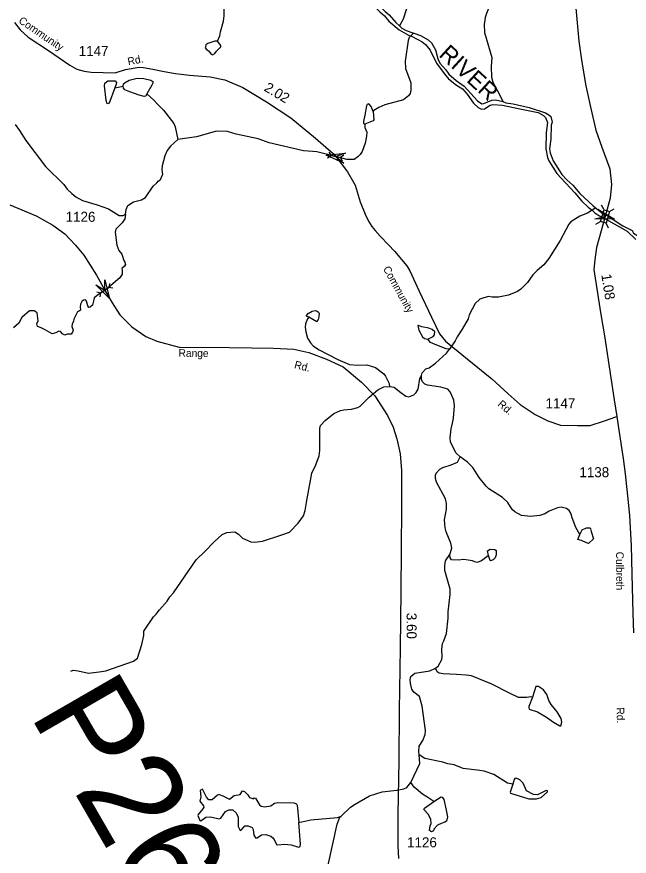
# Model space of a CAD drawing. Extents: x 2056842 to 2160602, y 826753 to 1016856.
# Drawn here: x 2071991 to 2079635, y 918502 to 928971 of the extents above; entities that cross this region are included whole.
import ezdxf

# ---------------------------------------------------------------- set-up
doc = ezdxf.new("R2010")
doc.units = 0
for name, color, linetype in [('Exist Hydrographic Creek Single Shore', 7, 'Continuous'), ('Exist Hydrographic Misc Water Feature', 7, 'Continuous'), ('Exist Hydrographic River Shore', 7, 'Continuous'), ('Exist Hydrographic River Shore Label', 7, 'Continuous'), ('Exist Road Secondary Mileage Hundredths English Label', 7, 'Continuous'), ('Exist Road Secondary Structure Pipe Attributed CELL', 7, 'Continuous'), ('Exist Road Secondary Structure Pipe CELL', 7, 'Continuous'), ('Exist Road Secondary Structure Pipe Number Label', 7, 'Continuous'), ('Exist Road Secondary Structure Standard Bridge Attributed CELL', 7, 'Continuous'), ('Exist Road Secondary Structure Standard Bridge CELL', 7, 'Continuous'), ('Exist Road Secondary Type 51 Attributed', 7, 'Continuous'), ('Exist Road Secondary Type 51 Label', 7, 'Continuous'), ('Exist Road Secondary Type 51 Number Label', 7, 'Continuous')]:
    doc.layers.add(name, color=color, linetype=linetype)

msp = doc.modelspace()

# ---------------------------------------------------------------- linework, layer by layer
at = {"layer": 'Exist Hydrographic Creek Single Shore'}
for points in [[(2078694, 930588), (2078660, 930556), (2078614, 930456), (2078527, 930326), (2078481, 930274), (2078405, 930146), (2078312, 930051), (2078232, 929913), (2078162, 929773), (2078047, 929633), (2078009, 929596), (2077975, 929454), (2077946, 929288), (2077899, 929128), (2077853, 929014), (2077835, 928962), (2077823, 928874), (2077830, 928774), (2077921, 928464), (2077913, 928352), (2077917, 928216), (2077933, 928156), (2078020, 927995), (2078056, 927915)], [(2076942, 928767), (2076890, 928713), (2076876, 928677), (2076839, 928417), (2076843, 928325), (2076909, 928149), (2076908, 928057), (2076900, 928013), (2076880, 927985), (2076816, 927937), (2076586, 927874), (2076510, 927840), (2076448, 927802), (2076439, 927787)], [(2076439, 927788), (2076415, 927854), (2076390, 927881), (2076379, 927885), (2076363, 927877), (2076355, 927861), (2076335, 927745)], [(2076439, 927788), (2076449, 927686), (2076437, 927672), (2076333, 927633)], [(2076335, 927745), (2076317, 927665), (2076317, 927641), (2076333, 927633)], [(2076333, 927633), (2076337, 927589), (2076362, 927533), (2076357, 927481), (2076340, 927397), (2076300, 927289), (2076278, 927255), (2076247, 927225), (2076201, 927193), (2076112, 927191), (2075972, 927228), (2075734, 927285), (2075686, 927293), (2075570, 927299), (2075140, 927401), (2075004, 927451), (2074728, 927506), (2074619, 927542), (2074484, 927543), (2074234, 927474), (2074002, 927440)], [(2074002, 927440), (2073910, 927359), (2073870, 927303), (2073837, 927235), (2073805, 927111), (2073801, 927067), (2073811, 927003), (2073776, 926931), (2073757, 926917)], [(2073350, 926511), (2073356, 926567), (2073378, 926619), (2073446, 926663), (2073546, 926689), (2073596, 926717), (2073695, 926859), (2073741, 926900), (2073759, 926924)], [(2073350, 926511), (2073338, 926452), (2073308, 926402), (2073227, 926321), (2073218, 926283), (2073239, 926123), (2073266, 926055), (2073302, 926012), (2073326, 925933), (2073340, 925912), (2073348, 925883), (2073335, 925862), (2073303, 925833), (2073305, 925809), (2073305, 925762), (2073279, 925714), (2073136, 925595), (2073090, 925562), (2073026, 925522), (2072956, 925466), (2072944, 925408), (2072937, 925376), (2072907, 925348), (2072889, 925344), (2072877, 925365), (2072863, 925425), (2072848, 925440), (2072824, 925438), (2072802, 925419), (2072787, 925385), (2072783, 925354), (2072787, 925314), (2072773, 925302), (2072748, 925291), (2072704, 925198), (2072700, 925173), (2072683, 925136), (2072680, 925110), (2072695, 925064), (2072687, 925037), (2072669, 925012), (2072648, 925014), (2072622, 925014), (2072590, 925001), (2072563, 925019), (2072536, 925046), (2072515, 925051), (2072478, 925028), (2072432, 925019), (2072347, 925065), (2072295, 925093), (2072251, 925109), (2072242, 925140), (2072258, 925180), (2072247, 925277), (2072209, 925304), (2072148, 925304), (2072054, 925221), (2072018, 925150), (2071951, 925093)]]:
    msp.add_lwpolyline(points, dxfattribs=at)
at = {"layer": 'Exist Hydrographic Misc Water Feature'}
for p, q in [((2073215, 928087), (2073317, 928104)), ((2079313, 926463), (2079339, 926501))]:
    msp.add_line(p, q, dxfattribs=at)
for points in [[(2074496, 928667), (2074524, 928732), (2074534, 928785), (2074573, 928916), (2074581, 928984), (2074579, 929092), (2074544, 929258), (2074562, 929360), (2074651, 929524), (2074707, 929598), (2074889, 929787), (2074988, 929833)], [(2076857, 929069), (2076815, 928943), (2076767, 928859)], [(2074496, 928667), (2074464, 928665), (2074376, 928637), (2074352, 928623), (2074346, 928597)], [(2074483, 928543), (2074536, 928596), (2074536, 928612), (2074496, 928667)], [(2074346, 928597), (2074344, 928583), (2074361, 928563), (2074385, 928545), (2074417, 928505), (2074435, 928497), (2074461, 928515), (2074483, 928543)], [(2073317, 928104), (2073325, 928135), (2073343, 928153), (2073394, 928181), (2073493, 928204), (2073578, 928201), (2073665, 928181), (2073688, 928163), (2073688, 928145), (2073678, 928120), (2073615, 928010)], [(2073105, 927929), (2073087, 928111), (2073091, 928143)], [(2073091, 928143), (2073129, 928171), (2073221, 928171), (2073235, 928151), (2073233, 928131), (2073215, 928087)], [(2073215, 928087), (2073145, 927895), (2073118, 927887), (2073105, 927929)], [(2073615, 928010), (2073603, 927981), (2073580, 927979), (2073519, 927992), (2073401, 928035), (2073340, 928061), (2073322, 928081), (2073317, 928104)], [(2073757, 927873), (2073749, 927881), (2073700, 927932), (2073615, 928010)], [(2073757, 927873), (2073823, 927805), (2073953, 927640), (2073968, 927600), (2074002, 927440)], [(2071970, 927628), (2072024, 927553), (2072105, 927429), (2072349, 927105), (2072577, 926880), (2072620, 926822), (2072678, 926766), (2072728, 926726), (2072810, 926678), (2072994, 926626), (2073134, 926575), (2073270, 926491), (2073318, 926491), (2073350, 926511)], [(2079339, 926501), (2079371, 926483), (2079555, 926365), (2079671, 926304), (2079687, 926272), (2079796, 926206), (2079827, 926202), (2079873, 926184), (2079915, 926193), (2079965, 926213), (2080063, 926293), (2080139, 926391), (2080189, 926467), (2080237, 926512), (2080352, 926582), (2080522, 926665), (2080584, 926681)], [(2079217, 926587), (2079116, 926524), (2079019, 926486), (2078907, 926413), (2078883, 926385), (2078773, 926183), (2078630, 925957), (2078571, 925876), (2078485, 925806), (2078433, 925754), (2078365, 925658), (2078283, 925573), (2078240, 925545), (2078128, 925499), (2078004, 925476), (2077924, 925476), (2077880, 925482), (2077808, 925462), (2077772, 925450), (2077710, 925394), (2077639, 925253), (2077623, 925203), (2077551, 925075), (2077487, 924981), (2077462, 924929), (2077390, 924825)], [(2079174, 926560), (2079208, 926524), (2079263, 926487), (2079313, 926463)], [(2075635, 925223), (2075609, 925237), (2075609, 925247), (2075629, 925271), (2075679, 925299)], [(2075679, 925299), (2075717, 925307), (2075739, 925301), (2075757, 925286), (2075763, 925270), (2075759, 925231)], [(2075635, 925223), (2075619, 925203), (2075595, 925143), (2075591, 925101), (2075599, 925043), (2075620, 924963), (2075656, 924903), (2075692, 924867), (2075756, 924822), (2075997, 924696), (2076143, 924635), (2076241, 924627), (2076361, 924629), (2076467, 924596), (2076571, 924518), (2076595, 924490), (2076639, 924398), (2076643, 924362)], [(2075759, 925231), (2075751, 925196), (2075735, 925167), (2075635, 925223)], [(2077177, 925070), (2077135, 925086), (2077047, 925104), (2077005, 925123), (2076997, 925119), (2077003, 925082), (2077009, 925062)], [(2077009, 925062), (2077054, 924980), (2077078, 924960), (2077120, 924950)], [(2077120, 924950), (2077186, 924982), (2077205, 925006), (2077207, 925042), (2077177, 925070)], [(2077390, 924825), (2077350, 924829), (2077214, 924886), (2077154, 924910), (2077120, 924950)], [(2077043, 924498), (2077049, 924530), (2077097, 924582), (2077137, 924594), (2077217, 924650), (2077354, 924777), (2077390, 924825)], [(2076643, 924362), (2076701, 924351), (2076768, 924297), (2076848, 924241), (2076884, 924233), (2076948, 924257), (2076976, 924287), (2077002, 924326), (2077023, 924458), (2077043, 924498)], [(2077524, 923485), (2077472, 923533), (2077404, 923669), (2077398, 923721), (2077411, 923833), (2077431, 923901), (2077441, 923965), (2077452, 924117), (2077444, 924189), (2077422, 924247), (2077398, 924293), (2077370, 924325), (2077285, 924352), (2077117, 924378), (2077085, 924390), (2077053, 924418), (2077043, 924446), (2077043, 924498)], [(2073773, 921575), (2073868, 921684), (2073902, 921738), (2073946, 921786), (2074228, 922199), (2074340, 922303), (2074454, 922422), (2074553, 922514), (2074613, 922538), (2074711, 922548), (2074759, 922519), (2074809, 922469), (2074914, 922423), (2074958, 922417), (2075058, 922433), (2075287, 922506), (2075393, 922543), (2075505, 922657), (2075571, 922747), (2075591, 922813), (2075612, 922937), (2075673, 923281), (2075725, 923382), (2075764, 923494), (2075772, 923562), (2075774, 923682), (2075773, 923838), (2075783, 923874), (2075839, 923938), (2075947, 924022), (2076031, 924062), (2076074, 924071), (2076170, 924079), (2076246, 924097), (2076276, 924113), (2076388, 924226), (2076496, 924318), (2076571, 924358), (2076643, 924362)], [(2077394, 922267), (2077420, 922345), (2077410, 922405), (2077349, 922547), (2077337, 922599), (2077331, 922697), (2077354, 922831), (2077354, 922903), (2077340, 922959), (2077229, 923168), (2077215, 923212), (2077215, 923256), (2077225, 923280), (2077271, 923328), (2077307, 923349), (2077411, 923383), (2077490, 923417), (2077524, 923485)], [(2079019, 922514), (2078967, 922602), (2078921, 922724), (2078908, 922782), (2078884, 922814), (2078850, 922839), (2078784, 922855), (2078738, 922847), (2078636, 922807), (2078580, 922773), (2078518, 922752), (2078403, 922738), (2078290, 922752), (2078206, 922795), (2078172, 922827), (2078120, 922915), (2078052, 922977), (2077881, 923082), (2077848, 923116), (2077763, 923224), (2077683, 923352), (2077616, 923418), (2077524, 923485)], [(2079019, 922514), (2079047, 922572), (2079103, 922598), (2079147, 922598), (2079153, 922586), (2079161, 922552)], [(2079161, 922552), (2079189, 922461), (2079127, 922402), (2079103, 922412)], [(2079103, 922412), (2079041, 922440), (2078995, 922454), (2079019, 922514)], [(2077878, 922254), (2077868, 922310), (2077900, 922330), (2077958, 922329)], [(2077958, 922329), (2077976, 922313), (2077976, 922261), (2077962, 922223)], [(2077219, 920846), (2077250, 920874), (2077294, 920955), (2077302, 920991), (2077298, 921079), (2077304, 921155), (2077321, 921187), (2077355, 921279), (2077377, 921469), (2077374, 921551), (2077402, 921767), (2077399, 921831), (2077333, 922067), (2077333, 922127), (2077340, 922187), (2077394, 922267)], [(2077878, 922254), (2077858, 922234), (2077792, 922186), (2077738, 922166), (2077706, 922172), (2077680, 922184), (2077570, 922203), (2077498, 922195), (2077418, 922197), (2077402, 922223), (2077394, 922267)], [(2077962, 922223), (2077938, 922197), (2077904, 922185), (2077900, 922190), (2077878, 922254)], [(2072667, 920808), (2072693, 920824), (2072759, 920816), (2072885, 920785), (2073019, 920801), (2073103, 920815), (2073449, 920934), (2073497, 920970), (2073552, 921142), (2073576, 921254), (2073578, 921307), (2073698, 921489), (2073729, 921519), (2073773, 921575)], [(2077014, 919766), (2077008, 919806), (2077014, 919874), (2077057, 919946), (2077087, 920022), (2077091, 920070), (2077050, 920372), (2077018, 920494), (2076945, 920548), (2076921, 920587), (2076903, 920655), (2076901, 920707), (2076909, 920743), (2076957, 920784), (2077145, 920816), (2077219, 920846)], [(2078428, 920486), (2078408, 920490), (2078356, 920480), (2078252, 920482), (2078140, 920537), (2077919, 920647), (2077667, 920750), (2077601, 920762), (2077477, 920769), (2077313, 920775), (2077261, 920787), (2077237, 920802), (2077219, 920846)], [(2078632, 920445), (2078607, 920517), (2078563, 920577), (2078503, 920618), (2078471, 920618), (2078428, 920486)], [(2078428, 920486), (2078382, 920368), (2078382, 920352), (2078388, 920338), (2078490, 920302), (2078602, 920237), (2078690, 920173)], [(2078690, 920173), (2078767, 920127), (2078783, 920127), (2078793, 920175), (2078786, 920219), (2078734, 920301), (2078662, 920393), (2078632, 920445)], [(2076911, 919422), (2077020, 919658), (2077014, 919766)], [(2078183, 919400), (2078117, 919413), (2077945, 919521), (2077825, 919564), (2077772, 919572), (2077562, 919594), (2077448, 919641), (2077372, 919655), (2077310, 919675), (2077084, 919722), (2077014, 919766)], [(2076039, 919003), (2076156, 919113), (2076216, 919153), (2076393, 919254), (2076550, 919306), (2076733, 919325), (2076823, 919343), (2076861, 919361), (2076911, 919422)], [(2077196, 919184), (2077110, 919244), (2077054, 919274), (2076951, 919362), (2076911, 919422)], [(2078183, 919400), (2078149, 919299), (2078153, 919287), (2078381, 919216), (2078478, 919217)], [(2078353, 919318), (2078309, 919412), (2078269, 919456), (2078225, 919474), (2078205, 919472), (2078197, 919460), (2078183, 919400)], [(2074516, 919270), (2074496, 919264), (2074430, 919204), (2074386, 919204), (2074360, 919237), (2074311, 919339), (2074280, 919321), (2074288, 919243), (2074274, 919189), (2074322, 919131), (2074324, 919115), (2074314, 919091), (2074254, 919023), (2074250, 919011), (2074277, 918949), (2074289, 918943), (2074351, 918991), (2074407, 918992), (2074519, 918970), (2074539, 918978), (2074594, 919058), (2074638, 919082), (2074686, 919080), (2074731, 919041), (2074755, 918991), (2074755, 918911)], [(2074516, 919270), (2074564, 919254), (2074636, 919218), (2074648, 919214), (2074704, 919259), (2074778, 919273), (2074808, 919319), (2074832, 919311), (2074876, 919267), (2074896, 919235), (2074944, 919219), (2074952, 919229), (2074972, 919227), (2075020, 919142), (2075040, 919126), (2075082, 919118), (2075160, 919130), (2075208, 919164), (2075248, 919172), (2075448, 919169), (2075484, 919155), (2075492, 919139), (2075513, 918921)], [(2078478, 919217), (2078534, 919233), (2078613, 919305), (2078613, 919317), (2078597, 919321), (2078491, 919267), (2078439, 919270), (2078353, 919318)], [(2077163, 918912), (2077159, 918960), (2077130, 919022), (2077072, 919084), (2077080, 919100), (2077196, 919184)], [(2077196, 919184), (2077288, 919241), (2077300, 919237), (2077320, 919211), (2077352, 919077), (2077366, 918993)], [(2075366, 917413), (2075435, 917463), (2075459, 917509), (2075549, 917617), (2075605, 917669), (2075662, 917752), (2075686, 917800), (2075732, 917990), (2075805, 918222), (2075882, 918410), (2075989, 918903), (2076023, 918989), (2076039, 919003)], [(2075513, 918921), (2075661, 918954), (2075995, 918983), (2076039, 919003)], [(2077366, 918993), (2077355, 918941), (2077333, 918925), (2077287, 918909), (2077243, 918889), (2077197, 918840), (2077191, 918820), (2077167, 918808), (2077143, 918824), (2077151, 918880), (2077163, 918912)], [(2074755, 918911), (2074753, 918871), (2074779, 918821), (2074795, 918831), (2074839, 918879), (2074879, 918883), (2074929, 918859), (2074943, 918837), (2074951, 918763), (2074971, 918733), (2074991, 918730), (2075045, 918770), (2075101, 918774), (2075163, 918750), (2075187, 918732), (2075203, 918712), (2075232, 918650), (2075244, 918642), (2075332, 918651), (2075416, 918643), (2075496, 918617), (2075510, 918613), (2075528, 918623), (2075532, 918651), (2075513, 918921)]]:
    msp.add_lwpolyline(points, dxfattribs=at)
at = {"layer": 'Exist Hydrographic River Shore'}
for points in [[(2074988, 929833), (2075069, 929777), (2075169, 929739), (2075321, 929736), (2075417, 929726), (2075553, 929697), (2075791, 929591), (2075963, 929492), (2076034, 929438), (2076190, 929335), (2076280, 929271), (2076521, 929034), (2076579, 928982), (2076635, 928918), (2076764, 928807), (2076882, 928741), (2076910, 928733)], [(2075548, 929746), (2075729, 929671), (2075813, 929627), (2075915, 929590), (2076226, 929371), (2076412, 929217), (2076589, 929036), (2076637, 928994), (2076723, 928898), (2076767, 928858)], [(2076767, 928858), (2076797, 928829), (2076849, 928801), (2077030, 928737), (2077126, 928684), (2077168, 928646), (2077216, 928558), (2077248, 928446), (2077273, 928394), (2077347, 928308), (2077383, 928256), (2077473, 928177), (2077573, 928107), (2077740, 927923), (2077796, 927884), (2077820, 927888), (2077920, 927932), (2077964, 927936), (2078056, 927915)], [(2076910, 928733), (2077006, 928685), (2077052, 928658), (2077092, 928624), (2077152, 928554), (2077229, 928394), (2077287, 928312), (2077343, 928244), (2077379, 928197), (2077478, 928117), (2077552, 928071), (2077612, 928007), (2077692, 927893), (2077748, 927840), (2077793, 927818), (2077828, 927824), (2077900, 927868), (2077934, 927876), (2078052, 927867), (2078268, 927823), (2078497, 927778), (2078565, 927738), (2078589, 927714), (2078615, 927654), (2078597, 927526), (2078592, 927326), (2078616, 927218), (2078632, 927175), (2078731, 927015), (2078954, 926776), (2079044, 926670), (2079124, 926596), (2079174, 926560)], [(2078056, 927915), (2078096, 927899), (2078188, 927887), (2078388, 927839), (2078589, 927774), (2078632, 927750), (2078657, 927726), (2078671, 927658), (2078661, 927619), (2078658, 927446), (2078640, 927326), (2078648, 927274), (2078685, 927176), (2078795, 927003), (2078855, 926939), (2078933, 926873), (2079020, 926766), (2079184, 926612), (2079294, 926527), (2079370, 926483), (2079555, 926365), (2079671, 926304)], [(2079313, 926463), (2079351, 926445), (2079607, 926296), (2079719, 926192)]]:
    msp.add_lwpolyline(points, dxfattribs=at)
at = {"layer": 'Exist Road Secondary Structure Pipe Attributed CELL'}
for points in [[(2076074, 927147), (2075852, 927247), (2076095, 927272), (2075972, 927228)], [(2073088, 925692), (2073150, 925456), (2072978, 925629), (2073090, 925562)]]:
    msp.add_lwpolyline(points, close=True, dxfattribs=at)
at = {"layer": 'Exist Road Secondary Structure Pipe CELL'}
for p, q in [((2075887, 927283), (2075913, 927240)), ((2076073, 927244), (2076032, 927215)), ((2075871, 927211), (2075913, 927240)), ((2075913, 927240), (2076032, 927215)), ((2076058, 927172), (2076032, 927215)), ((2073039, 925528), (2073140, 925596)), ((2073148, 925646), (2073140, 925596)), ((2073189, 925585), (2073140, 925596)), ((2072990, 925539), (2073039, 925528)), ((2073031, 925478), (2073039, 925528))]:
    msp.add_line(p, q, dxfattribs=at)
at = {"layer": 'Exist Road Secondary Structure Standard Bridge Attributed CELL'}
msp.add_lwpolyline([(2079242, 926572), (2079451, 926446), (2079207, 926451), (2079334, 926480)], close=True, dxfattribs=at)
at = {"layer": 'Exist Road Secondary Structure Standard Bridge CELL'}
for p, q in [((2079321, 926562), (2079289, 926623)), ((2079387, 926542), (2079448, 926575)), ((2079216, 926385), (2079277, 926417)), ((2079377, 926336), (2079345, 926397))]:
    msp.add_line(p, q, dxfattribs=at)
msp.add_lwpolyline([(2079277, 926417), (2079321, 926562), (2079388, 926542), (2079345, 926397)], close=True, dxfattribs=at)
at = {"layer": 'Exist Road Secondary Type 51 Attributed'}
for points in [[(2078920, 929604), (2078947, 929410), (2078965, 929126), (2079007, 928667), (2079042, 928407), (2079095, 928109), (2079154, 927827), (2079217, 927556), (2079293, 927343), (2079394, 927075), (2079413, 926881), (2079398, 926708), (2079334, 926480)], [(2071961, 928899), (2072034, 928810), (2072135, 928717), (2072385, 928550), (2072655, 928367), (2072741, 928317), (2072831, 928292), (2072919, 928281), (2073070, 928278), (2073221, 928274), (2073350, 928314), (2073520, 928343), (2073574, 928340), (2073688, 928318), (2073832, 928289), (2073970, 928262), (2074148, 928241), (2074404, 928222), (2074587, 928184), (2074812, 928089), (2075108, 927911), (2075410, 927712), (2075721, 927456), (2075946, 927263), (2075972, 927228), (2076119, 927036), (2076216, 926871), (2076277, 926662), (2076341, 926508), (2076382, 926423), (2076422, 926357), (2076465, 926304), (2076525, 926233), (2076629, 926126), (2076704, 926050), (2076858, 925864), (2076898, 925804), (2077012, 925548), (2077165, 925226), (2077267, 925019), (2077343, 924924), (2077592, 924721), (2077920, 924457), (2078125, 924267), (2078272, 924134), (2078462, 924012), (2078620, 923931), (2078776, 923877), (2078990, 923872), (2079147, 923874), (2079325, 923932), (2079480, 923986)], [(2071905, 926625), (2072233, 926487), (2072443, 926372), (2072589, 926264), (2072723, 926122), (2072828, 925999), (2072986, 925749), (2073090, 925562), (2073182, 925403), (2073278, 925254), (2073427, 925103), (2073603, 924983), (2073740, 924927), (2074018, 924852), (2074644, 924846), (2075197, 924838), (2075449, 924825), (2075636, 924784), (2075858, 924701), (2076063, 924606), (2076293, 924413), (2076461, 924245), (2076617, 923999), (2076689, 923854), (2076736, 923707), (2076778, 923522), (2076794, 923314), (2076791, 922860), (2076787, 922318), (2076784, 921809), (2076778, 921096), (2076764, 920323), (2076760, 919691), (2076748, 919022), (2076745, 918633), (2076756, 918475)], [(2079334, 926480), (2079227, 926092), (2079207, 925941), (2079194, 925819), (2079278, 925283), (2079326, 924993), (2079406, 924470), (2079447, 924195), (2079480, 923986)], [(2079480, 923986), (2079506, 923816), (2079560, 923464), (2079584, 923273), (2079623, 922919), (2079640, 922749), (2079657, 922377), (2079668, 922019), (2079679, 921535), (2079689, 921290)]]:
    msp.add_lwpolyline(points, dxfattribs=at)

# ---------------------------------------------------------------- texts
at = {"layer": 'Exist Hydrographic River Shore Label'}
msp.add_text('RIVER', height=210, rotation=317.4763, dxfattribs=at).set_placement((2077248, 928487))
at = {"layer": 'Exist Road Secondary Mileage Hundredths English Label'}
for s, rotation, p in [('2.02', 329.1315, (2075068, 928055)), ('1.08', 279.1808, (2079285, 925755)), ('3.60', 270.1666, (2076856, 921537))]:
    msp.add_text(s, height=125, rotation=rotation, dxfattribs=at).set_placement(p)
at = {"layer": 'Exist Road Secondary Structure Pipe Number Label'}
msp.add_text('P267', height=1230.3, rotation=300, dxfattribs=at).set_placement((2072142, 920276))
at = {"layer": 'Exist Road Secondary Type 51 Label'}
for s, rotation, p in [('Community', 325.646, (2072005, 928902)), ('Rd.', 11.2946, (2073384, 928365)), ('Community', 298.9457, (2076559, 925830)), ('Range', 359.4883, (2074010, 924731)), ('Rd.', 345.9076, (2075448, 924591)), ('Rd.', 318.6202, (2077986, 924129)), ('Culbreth', 270.1605, (2079471, 922300)), ('Rd.', 271.4467, (2079477, 920357))]:
    msp.add_text(s, height=95, rotation=rotation, dxfattribs=at).set_placement(p)
at = {"layer": 'Exist Road Secondary Type 51 Number Label'}
for s, p in [('1147', (2072764, 928482)), ('1126', (2072601, 926414)), ('1147', (2078590, 924087)), ('1138', (2079013, 923229)), ('1126', (2076862, 918613))]:
    msp.add_text(s, height=125, dxfattribs=at).set_placement(p)

doc.saveas('drawing.dxf')
